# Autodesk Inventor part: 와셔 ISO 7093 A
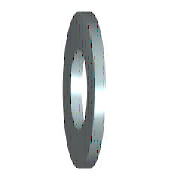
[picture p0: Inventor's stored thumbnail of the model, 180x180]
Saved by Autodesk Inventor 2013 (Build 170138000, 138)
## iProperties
Created: 2012-02
Part Number: 와셔 ISO 7093 A
Material: 스테인리스강
Description: 평면 와셔 - 대형 시리즈 - 제품 등급 A
Document SubType Name: Modeling
Standard: ISO 7093 A
Designer: mduedu
Standard Revision: First Edition 2000-06-01
Standards Organization: ISO
Language: ko-KR
Size Designation: ST 4 - 140 HV - A
Categories: <MemberInstance><Categories><Category DisplayName="조임쇠" InternalName="e4da775c-781d-43d5-af7c-5136215cf5a6" Mnemonic="FSTN"><Category DisplayName="와셔" InternalN
Density: 8.08 g/cm^3
Mass: 0.796489 g
Surface Area: 2.48359 cm^2
Volume: 0.0985753 cm^3
IsCustomPart: 1
Author: mduedu
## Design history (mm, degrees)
sketch "스케치"
  geometry: C1 r 6 at (0, 0); C2 r 2.15 at (0, 0); 1 further point
  constraints: 2 centre point, 2 coincident
  dimensions: "d0" = 4.3 diameter of C2 (= SD1); "d1" = 12 diameter of C1 (= SD2)
extrude "본체" new body sketch "스케치" distance "d2" = 1 (= SD); taper "d3" = 0 deg
workaxis "Work Axis1"
workplane "Work Plane1"
body "Solid1"
other parameters: "SD1" = 4.3 [user parameter; used in 1 equation term], "SD2" = 12 [user parameter; used in 1 equation term], "SD" = 1 [user parameter; used in 1 equation term], "d4" = 0, "d5" = 0, "d6" = 0, "d7" = 0, "NND" = 4 [user parameter]
